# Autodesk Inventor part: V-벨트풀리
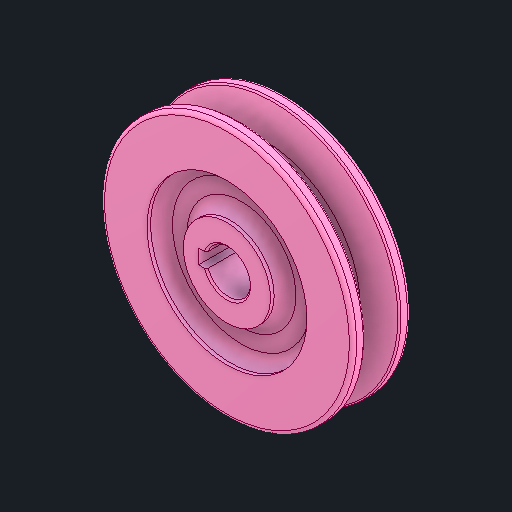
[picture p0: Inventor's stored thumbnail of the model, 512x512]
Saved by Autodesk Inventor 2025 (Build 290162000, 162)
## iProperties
Created: 2025-08
Part Number: V-벨트풀리
Material: 강철, 연강
Document SubType Name: Modeling
Designer: infra17
Density: 7.86 g/cm^3
Appearance: 기본값
Author: jhkim
Sending System: Autodesk Inventor 2026
Preprocessor: ST-DEVELOPER v20.1
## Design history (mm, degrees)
feature "Solid1"
node "솔리드1"
